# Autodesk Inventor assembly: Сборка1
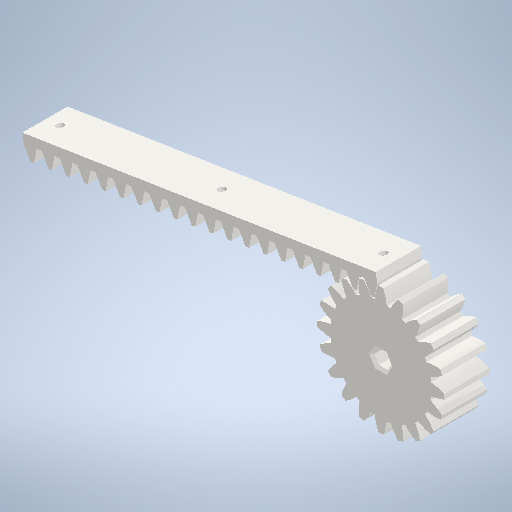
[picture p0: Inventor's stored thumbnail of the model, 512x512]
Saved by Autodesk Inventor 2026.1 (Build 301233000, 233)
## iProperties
Created: 2026-01
Part Number: Сборка1
Document SubType Name: Assembly
Designer: Yury Melnikov
Author: Yury Melnikov
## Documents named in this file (2)
- C:\Users\user\Documents\Проекты\ВсОШ_РОБО\Робот\Сборка1.iam
- C:\Users\user\Documents\Проекты\ВсОШ_РОБО\Робот\Сборка1\Мастер проектирования\Цилиндрическое зубчатое зацепление3.iam
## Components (1 placed, 1 different names)
1. Цилиндрическое зубчатое зацепление:1 [sub-assembly]
